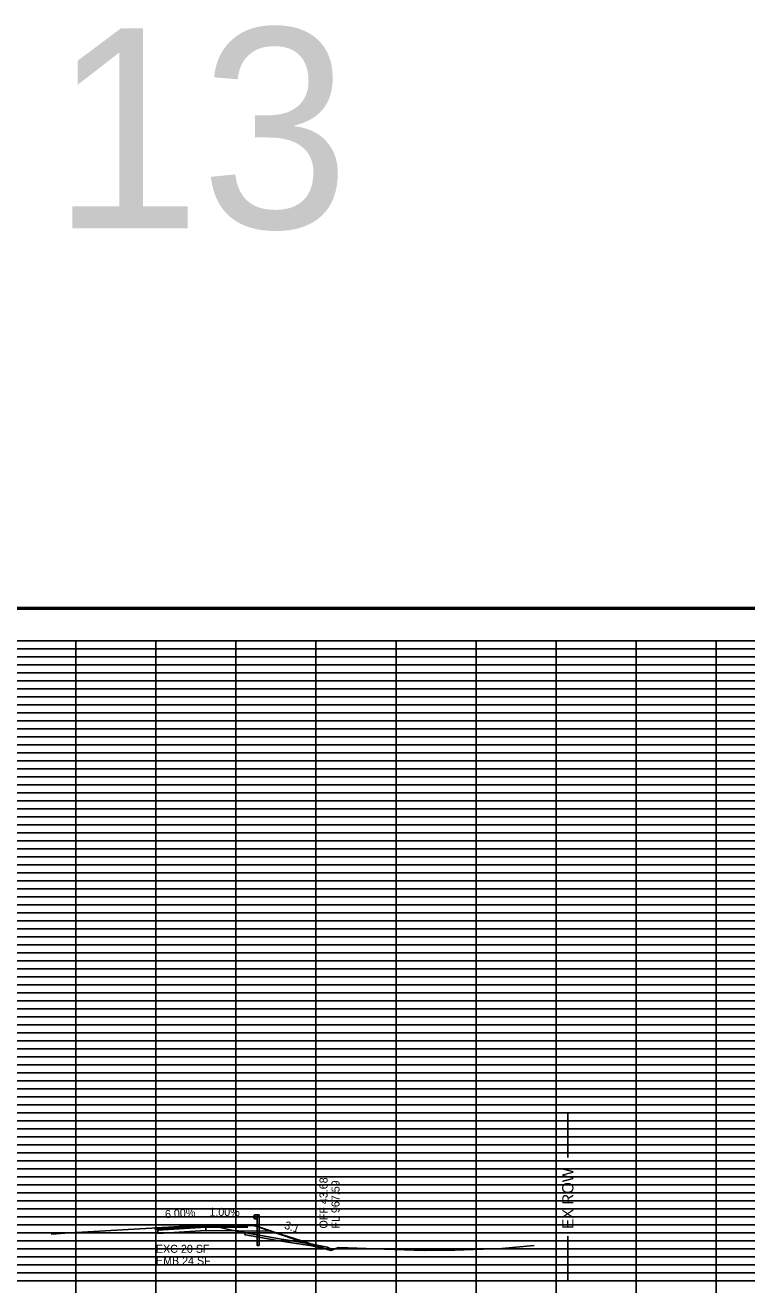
# Model space of a CAD drawing. Extents: x 2313580 to 2322968, y 282099 to 303247.
# Drawn here: x 2317959.8 to 2318140.1, y 287846.7 to 288161.5 of the extents above; entities that cross this region are included whole.
import ezdxf

# ---------------------------------------------------------------- set-up
doc = ezdxf.new("R2010")
doc.units = 0
for name, color, linetype in [('DESIGN - CENTERLINE - Proposed', 7, 'Continuous'), ('DESIGN - DRAINAGE - Text', 7, 'Continuous'), ('DESIGN - EARTHWORK - Excavation Limit Lines', 7, 'Continuous'), ('DESIGN - EARTHWORK - Shapes', 7, 'Continuous'), ('DESIGN - SCRATCH - User 1', 7, 'Continuous'), ('DESIGN - SCRATCH - User 5', 7, 'Continuous'), ('DESIGN - SHEET - Light Grid', 7, 'Continuous'), ('DESIGN - SHEET - Linework', 7, 'Continuous'), ('DESIGN - SHEET - Plot Shape', 7, 'Continuous'), ('DESIGN - TYPICAL - Finished Grade and Subgrade', 7, 'Continuous'), ('DESIGN - TYPICAL - Finished Grade Slopes Text', 7, 'Continuous'), ('DESIGN - TYPICAL - Guardrail', 7, 'Continuous'), ('Scratch Level', 7, 'Continuous'), ('SURVEY - GROUND - Top of Ground', 7, 'Continuous'), ('SURVEY - PROPERTY - ROW Lines Text', 7, 'Continuous')]:
    doc.layers.add(name, color=color, linetype=linetype)

# ---------------------------------------------------------------- blocks, each defined once
blk = doc.blocks.new('GRTYP')
at = {"layer": 'DESIGN - CENTERLINE - Proposed'}
for p, q in [((0.162, 0.37), (0.162, 0.37)), ((0.162, 0.37), (0.162, 0.37)), ((0.264, 0.37), (0.264, 0.37)), ((0.264, 0.37), (0.264, 0.37))]:
    blk.add_line(p, q, dxfattribs=at)
for points in [[(0.059, 0.567), (0.04, 0.563), (0.004, 0.539), (0, 0.531), (0.004, 0.523), (0.055, 0.492), (0.059, 0.484), (0.059, 0.464), (0.055, 0.456), (0.004, 0.425), (0, 0.417), (0.004, 0.409), (0.04, 0.385), (0.059, 0.382)], [(0.162, 0.374), (0.059, 0.374), (0.059, 0.574), (0.162, 0.574)], [(0.264, -0.126), (0.264, 0.574), (0.162, 0.574), (0.162, -0.075)], [(0.162, -0.075), (0.162, -0.949), (0.264, -0.949), (0.264, -0.122)]]:
    blk.add_lwpolyline(points, dxfattribs=at)

msp = doc.modelspace()

# ---------------------------------------------------------------- linework, layer by layer
at = {"layer": 'DESIGN - EARTHWORK - Shapes'}
for points in [[(2317992.31, 287860.88), (2317992.31, 287860.88), (2317997.49, 287861.18), (2318006.42, 287861.16), (2318007.84, 287861.15), (2318009.62, 287860.72), (2318010.94, 287860.43), (2318012.34, 287860.17), (2318004.93, 287860.25), (2317992.93, 287859.52), (2317992.93, 287860.35), (2317992.93, 287860.6), (2317992.31, 287860.57), (2317992.31, 287860.78)], [(2318012.34, 287860.17), (2318014.93, 287859.69), (2318023.84, 287858.07), (2318030.91, 287856.97), (2318021.79, 287859.94), (2318021.34, 287860.08), (2318021.16, 287860.08)], [(2318035, 287855.64), (2318035.2, 287855.57), (2318035.13, 287855.61)], [(2318035.47, 287855.49), (2318036.16, 287855.26), (2318035.92, 287855.75), (2318035.47, 287856)]]:
    msp.add_lwpolyline(points, close=True, dxfattribs=at)
at = {"layer": 'DESIGN - SCRATCH - User 1'}
msp.add_lwpolyline([(2318014.93, 287861.54), (2318016.93, 287861.52), (2318033.95, 287855.74)], dxfattribs=at)
msp.add_lwpolyline([(2318014.93, 287861.54), (2318016.93, 287861.52), (2318033.95, 287855.74)], dxfattribs=at)
msp.add_lwpolyline([(2318014.93, 287861.54), (2318016.93, 287861.52), (2318033.95, 287855.74)], dxfattribs=at)
msp.add_lwpolyline([(2318014.93, 287861.54), (2318016.93, 287861.52), (2318033.95, 287855.74)], dxfattribs=at)
at = {"layer": 'DESIGN - SCRATCH - User 5'}
for points in [[(2318030.91, 287856.97), (2318023.84, 287858.07), (2318014.93, 287859.69), (2318014.71, 287859.73), (2318014.71, 287859.22), (2318014.84, 287859.19), (2318023.75, 287857.58), (2318030.91, 287856.46)], [(2318030.91, 287856.97), (2318023.84, 287858.07), (2318014.93, 287859.69), (2318014.71, 287859.73), (2318014.71, 287859.22), (2318014.84, 287859.19), (2318023.75, 287857.58), (2318030.91, 287856.46)], [(2318030.91, 287856.46), (2318031.46, 287856.38), (2318035.13, 287855.61), (2318035.47, 287855.43), (2318035.47, 287856), (2318035.3, 287856.09), (2318031.55, 287856.87), (2318030.91, 287856.97)], [(2318030.91, 287856.46), (2318031.46, 287856.38), (2318035.13, 287855.61), (2318035.47, 287855.43), (2318035.47, 287856), (2318035.3, 287856.09), (2318031.55, 287856.87), (2318030.91, 287856.97)]]:
    msp.add_lwpolyline(points, close=True, dxfattribs=at)
at = {"layer": 'DESIGN - SHEET - Light Grid'}
for p, q in [((2317832.48, 288005.67), (2317992.48, 288005.67)), ((2317992.48, 288005.67), (2318152.48, 288005.67)), ((2317832.48, 288003.67), (2317992.48, 288003.67)), ((2317832.48, 288001.67), (2317992.48, 288001.67)), ((2317992.48, 288003.67), (2318152.48, 288003.67)), ((2317992.48, 288001.67), (2318152.48, 288001.67)), ((2317832.48, 287999.67), (2317992.48, 287999.67)), ((2317992.48, 287999.67), (2318152.48, 287999.67)), ((2317832.48, 287997.67), (2317992.48, 287997.67)), ((2317832.48, 287995.67), (2317992.48, 287995.67)), ((2317992.48, 287997.67), (2318152.48, 287997.67)), ((2317992.48, 287995.67), (2318152.48, 287995.67)), ((2317832.48, 287993.67), (2317992.48, 287993.67)), ((2317832.48, 287991.67), (2317992.48, 287991.67)), ((2317992.48, 287993.67), (2318152.48, 287993.67)), ((2317992.48, 287991.67), (2318152.48, 287991.67)), ((2317832.48, 287989.67), (2317992.48, 287989.67)), ((2317992.48, 287989.67), (2318152.48, 287989.67)), ((2317832.48, 287985.67), (2317992.48, 287985.67)), ((2317992.48, 287985.67), (2318152.48, 287985.67)), ((2317832.48, 287983.67), (2317992.48, 287983.67)), ((2317992.48, 287983.67), (2318152.48, 287983.67)), ((2317832.48, 287981.67), (2317992.48, 287981.67)), ((2317832.48, 287979.67), (2317992.48, 287979.67)), ((2317992.48, 287981.67), (2318152.48, 287981.67)), ((2317992.48, 287979.67), (2318152.48, 287979.67)), ((2317832.48, 287977.67), (2317992.48, 287977.67)), ((2317992.48, 287977.67), (2318152.48, 287977.67)), ((2317832.48, 287975.67), (2317992.48, 287975.67)), ((2317832.48, 287973.67), (2317992.48, 287973.67)), ((2317992.48, 287975.67), (2318152.48, 287975.67)), ((2317992.48, 287973.67), (2318152.48, 287973.67)), ((2317832.48, 287971.67), (2317992.48, 287971.67)), ((2317832.48, 287969.67), (2317992.48, 287969.67)), ((2317992.48, 287971.67), (2318152.48, 287971.67)), ((2317992.48, 287969.67), (2318152.48, 287969.67)), ((2317832.48, 287965.67), (2317992.48, 287965.67)), ((2317832.48, 287963.67), (2317992.48, 287963.67)), ((2317992.48, 287965.67), (2318152.48, 287965.67)), ((2317992.48, 287963.67), (2318152.48, 287963.67)), ((2317832.48, 287961.67), (2317992.48, 287961.67)), ((2317992.48, 287961.67), (2318152.48, 287961.67)), ((2317832.48, 287959.67), (2317992.48, 287959.67)), ((2317832.48, 287957.67), (2317992.48, 287957.67)), ((2317992.48, 287959.67), (2318152.48, 287959.67)), ((2317992.48, 287957.67), (2318152.48, 287957.67)), ((2317832.48, 287955.67), (2317992.48, 287955.67)), ((2317992.48, 287955.67), (2318152.48, 287955.67)), ((2317832.48, 287953.67), (2317992.48, 287953.67)), ((2317832.48, 287951.67), (2317992.48, 287951.67)), ((2317992.48, 287953.67), (2318152.48, 287953.67)), ((2317992.48, 287951.67), (2318152.48, 287951.67)), ((2317832.48, 287949.67), (2317992.48, 287949.67)), ((2317992.48, 287949.67), (2318152.48, 287949.67)), ((2317832.48, 287945.67), (2317992.48, 287945.67)), ((2317992.48, 287945.67), (2318152.48, 287945.67)), ((2317832.48, 287943.67), (2317992.48, 287943.67)), ((2317832.48, 287941.67), (2317992.48, 287941.67)), ((2317992.48, 287943.67), (2318152.48, 287943.67)), ((2317992.48, 287941.67), (2318152.48, 287941.67)), ((2317832.48, 287939.67), (2317992.48, 287939.67)), ((2317992.48, 287939.67), (2318152.48, 287939.67)), ((2317832.48, 287937.67), (2317992.48, 287937.67)), ((2317832.48, 287935.67), (2317992.48, 287935.67)), ((2317992.48, 287937.67), (2318152.48, 287937.67)), ((2317992.48, 287935.67), (2318152.48, 287935.67)), ((2317832.48, 287933.67), (2317992.48, 287933.67)), ((2317992.48, 287933.67), (2318152.48, 287933.67)), ((2317832.48, 287931.67), (2317992.48, 287931.67)), ((2317832.48, 287929.67), (2317992.48, 287929.67)), ((2317992.48, 287931.67), (2318152.48, 287931.67)), ((2317992.48, 287929.67), (2318152.48, 287929.67)), ((2317832.48, 287925.67), (2317992.48, 287925.67)), ((2317992.48, 287925.67), (2318152.48, 287925.67)), ((2317832.48, 287923.67), (2317992.48, 287923.67)), ((2317992.48, 287923.67), (2318152.48, 287923.67)), ((2317832.48, 287921.67), (2317992.48, 287921.67)), ((2317832.48, 287919.67), (2317992.48, 287919.67)), ((2317992.48, 287921.67), (2318152.48, 287921.67)), ((2317992.48, 287919.67), (2318152.48, 287919.67)), ((2317832.48, 287917.67), (2317992.48, 287917.67)), ((2317992.48, 287917.67), (2318152.48, 287917.67)), ((2317832.48, 287915.67), (2317992.48, 287915.67)), ((2317832.48, 287913.67), (2317992.48, 287913.67)), ((2317992.48, 287915.67), (2318152.48, 287915.67)), ((2317992.48, 287913.67), (2318152.48, 287913.67)), ((2317832.48, 287911.67), (2317992.48, 287911.67)), ((2317992.48, 287911.67), (2318152.48, 287911.67)), ((2317832.48, 287909.67), (2317992.48, 287909.67)), ((2317992.48, 287909.67), (2318152.48, 287909.67)), ((2317832.48, 287905.67), (2317992.48, 287905.67)), ((2317832.48, 287903.67), (2317992.48, 287903.67)), ((2317992.48, 287905.67), (2318152.48, 287905.67)), ((2317992.48, 287903.67), (2318152.48, 287903.67)), ((2317832.48, 287901.67), (2317992.48, 287901.67)), ((2317992.48, 287901.67), (2318152.48, 287901.67)), ((2317832.48, 287899.67), (2317992.48, 287899.67)), ((2317832.48, 287897.67), (2317992.48, 287897.67)), ((2317992.48, 287899.67), (2318152.48, 287899.67)), ((2317992.48, 287897.67), (2318152.48, 287897.67)), ((2317832.48, 287895.67), (2317992.48, 287895.67)), ((2317992.48, 287895.67), (2318152.48, 287895.67)), ((2317832.48, 287893.67), (2317992.48, 287893.67)), ((2317832.48, 287891.67), (2317992.48, 287891.67)), ((2317992.48, 287893.67), (2318152.48, 287893.67)), ((2317992.48, 287891.67), (2318152.48, 287891.67)), ((2317832.48, 287889.67), (2317992.48, 287889.67)), ((2317992.48, 287889.67), (2318152.48, 287889.67)), ((2317832.48, 287885.67), (2317992.48, 287885.67)), ((2317992.48, 287885.67), (2318152.48, 287885.67)), ((2317832.48, 287883.67), (2317992.48, 287883.67)), ((2317832.48, 287881.67), (2317992.48, 287881.67)), ((2317992.48, 287883.67), (2318152.48, 287883.67)), ((2317992.48, 287881.67), (2318152.48, 287881.67)), ((2317832.48, 287879.67), (2317992.48, 287879.67)), ((2317992.48, 287879.67), (2318152.48, 287879.67)), ((2317832.48, 287877.67), (2317992.48, 287877.67)), ((2317832.48, 287875.67), (2317992.48, 287875.67)), ((2317992.48, 287877.67), (2318152.48, 287877.67)), ((2317992.48, 287875.67), (2318152.48, 287875.67)), ((2317832.48, 287873.67), (2317992.48, 287873.67)), ((2317992.48, 287873.67), (2318152.48, 287873.67)), ((2317832.48, 287871.67), (2317992.48, 287871.67)), ((2317832.48, 287869.67), (2317992.48, 287869.67)), ((2317992.48, 287871.67), (2318152.48, 287871.67)), ((2317992.48, 287869.67), (2318152.48, 287869.67)), ((2317832.48, 287865.67), (2317992.48, 287865.67)), ((2317992.48, 287865.67), (2318152.48, 287865.67)), ((2317832.48, 287863.67), (2317992.48, 287863.67)), ((2317992.48, 287863.67), (2318152.48, 287863.67)), ((2317832.48, 287861.67), (2317992.48, 287861.67)), ((2317832.48, 287859.67), (2317992.48, 287859.67)), ((2317992.48, 287861.67), (2318152.48, 287861.67)), ((2317992.48, 287859.67), (2318152.48, 287859.67)), ((2317832.48, 287857.67), (2317992.48, 287857.67)), ((2317992.48, 287857.67), (2318152.48, 287857.67)), ((2317832.48, 287855.67), (2317992.48, 287855.67)), ((2317832.48, 287853.67), (2317992.48, 287853.67)), ((2317992.48, 287855.67), (2318152.48, 287855.67)), ((2317992.48, 287853.67), (2318152.48, 287853.67)), ((2317832.48, 287851.67), (2317992.48, 287851.67)), ((2317992.48, 287851.67), (2318152.48, 287851.67)), ((2317832.48, 287849.67), (2317992.48, 287849.67)), ((2317992.48, 287849.67), (2318152.48, 287849.67))]:
    msp.add_line(p, q, dxfattribs=at)
at = {"layer": 'DESIGN - SHEET - Linework'}
for p, q in [((2317636.02, 288015.95), (2318316.82, 288015.95)), ((2317972.48, 287587.67), (2317972.48, 288007.67)), ((2317992.48, 287587.67), (2317992.48, 288007.67)), ((2318012.48, 287587.67), (2318012.48, 288007.67)), ((2318032.48, 287587.67), (2318032.48, 288007.67)), ((2318052.48, 287587.67), (2318052.48, 288007.67)), ((2318072.48, 287587.67), (2318072.48, 288007.67)), ((2318092.48, 287587.67), (2318092.48, 288007.67)), ((2318112.48, 287587.67), (2318112.48, 288007.67)), ((2318132.48, 287587.67), (2318132.48, 288007.67)), ((2317672.48, 287987.67), (2318232.48, 287987.67)), ((2317672.48, 287967.67), (2318312.48, 287967.67)), ((2317672.48, 287947.67), (2318312.48, 287947.67)), ((2317672.48, 287927.67), (2318312.48, 287927.67)), ((2317672.48, 287907.67), (2318312.48, 287907.67)), ((2317672.48, 287887.67), (2318312.48, 287887.67)), ((2317672.48, 287867.67), (2318312.48, 287867.67)), ((2317672.48, 287847.67), (2318312.48, 287847.67))]:
    msp.add_line(p, q, dxfattribs=at)
msp.add_lwpolyline([(2317672.48, 288007.67), (2317672.48, 287587.67), (2318312.48, 287587.67), (2318312.48, 288007.67), (2317672.48, 288007.67)], dxfattribs=at)
at = {"layer": 'DESIGN - SHEET - Plot Shape'}
for points in [[(2317636.42, 288015.55), (2318316.42, 288015.55), (2318316.42, 287579.79), (2317636.42, 287579.79)], [(2317655.48, 288007.67), (2318312.48, 288007.67), (2318312.48, 287582.67), (2317655.48, 287582.67)]]:
    msp.add_lwpolyline(points, close=True, dxfattribs=at)
at = {"layer": 'DESIGN - TYPICAL - Finished Grade and Subgrade'}
msp.add_lwpolyline([(2317992.31, 287860.88), (2317992.39, 287860.89), (2317992.93, 287860.92), (2317994.38, 287861), (2318004.93, 287861.64), (2318006.15, 287861.62), (2318014.93, 287861.54), (2318015.18, 287861.53), (2318016.93, 287861.52), (2318017.37, 287861.38), (2318021.34, 287860.08), (2318021.79, 287859.94), (2318036.16, 287855.26)], dxfattribs=at)
for points in [[(2317992.93, 287860.92), (2317992.31, 287860.88), (2317992.31, 287860.78), (2317992.93, 287860.81)], [(2317992.93, 287860.81), (2317992.93, 287860.6), (2317992.31, 287860.57), (2317992.31, 287860.78)], [(2317992.93, 287860.92), (2318004.93, 287861.64), (2318004.93, 287861.54), (2317992.93, 287860.81)], [(2317992.93, 287860.81), (2318004.93, 287861.54), (2318004.93, 287861.33), (2317992.93, 287860.6)], [(2317992.93, 287860.6), (2318004.93, 287861.33), (2318004.93, 287861.08), (2317992.93, 287860.35)], [(2317992.93, 287860.35), (2318004.93, 287861.08), (2318004.93, 287860.25), (2317992.93, 287859.52)], [(2318004.93, 287861.64), (2318014.93, 287861.54), (2318014.93, 287861.44), (2318004.93, 287861.54)], [(2318004.93, 287861.08), (2318015.24, 287860.98), (2318015.24, 287861.23), (2318015.04, 287861.23), (2318015.04, 287861.44), (2318014.93, 287861.44), (2318014.93, 287861.54), (2318016.93, 287861.52), (2318021.34, 287860.08), (2318004.93, 287860.25)], [(2318004.93, 287861.54), (2318015.04, 287861.44), (2318015.04, 287861.23), (2318004.93, 287861.33)], [(2318004.93, 287861.33), (2318015.24, 287861.23), (2318015.24, 287860.98), (2318004.93, 287861.08)]]:
    msp.add_lwpolyline(points, close=True, dxfattribs=at)
at = {"layer": 'Scratch Level'}
for points in [[(2317992.31, 287860.88), (2317992.31, 287860.88), (2317997.49, 287861.18), (2318006.42, 287861.16), (2318007.84, 287861.15), (2318009.62, 287860.72), (2318010.94, 287860.43), (2318012.34, 287860.17), (2318004.93, 287860.25), (2317992.93, 287859.52), (2317992.93, 287860.35), (2317992.93, 287860.6), (2317992.31, 287860.57), (2317992.31, 287860.78)], [(2318012.34, 287860.17), (2318014.93, 287859.69), (2318023.84, 287858.07), (2318030.91, 287856.97), (2318021.79, 287859.94), (2318021.34, 287860.08), (2318021.16, 287860.08)], [(2318035, 287855.64), (2318035.2, 287855.57), (2318035.13, 287855.61)], [(2318035.47, 287855.49), (2318036.16, 287855.26), (2318035.92, 287855.75), (2318035.47, 287856)]]:
    msp.add_lwpolyline(points, close=True, dxfattribs=at)
at = {"layer": 'SURVEY - GROUND - Top of Ground'}
msp.add_lwpolyline([(2317966.27, 287859.3), (2317967.53, 287859.41), (2317969.72, 287859.6), (2317988.45, 287860.67), (2317997.49, 287861.18), (2318006.42, 287861.16), (2318007.84, 287861.15), (2318009.62, 287860.72), (2318010.94, 287860.43), (2318014.93, 287859.69), (2318023.84, 287858.07), (2318031.55, 287856.87), (2318035.3, 287856.09), (2318035.92, 287855.75), (2318036.16, 287855.26), (2318038.14, 287855.96), (2318049.58, 287855.54), (2318059.49, 287855.24), (2318067.21, 287855.32), (2318078.89, 287855.73), (2318087.04, 287856.5)], dxfattribs=at)
at = {"layer": 'SURVEY - PROPERTY - ROW Lines Text'}
for p, q in [((2318095.41, 287889.67), (2318095.41, 287878.47)), ((2318095.41, 287847.67), (2318095.41, 287858.87))]:
    msp.add_line(p, q, dxfattribs=at)

# ---------------------------------------------------------------- block references
at = {"layer": 'DESIGN - TYPICAL - Guardrail', "xscale": 5, "yscale": 5}
msp.add_blockref('GRTYP', (2318016.93, 287861.26), dxfattribs=at)

# ---------------------------------------------------------------- texts
at = {"layer": 'DESIGN - DRAINAGE - Text'}
for s, p in [("OFF 43.68'", (2318035.36, 287860.74)), ('FL 967.59', (2318038.36, 287860.74))]:
    msp.add_text(s, height=2, rotation=90, dxfattribs=at).set_placement(p)
at = {"layer": 'DESIGN - EARTHWORK - Excavation Limit Lines'}
for s, p in [('EXC 20 SF', (2317992.48, 287854.67)), ('EMB 24 SF', (2317992.48, 287851.67))]:
    msp.add_text(s, height=2, dxfattribs=at).set_placement(p)
at = {"layer": 'DESIGN - SCRATCH - User 1'}
msp.add_text('13', height=50, dxfattribs=at).set_placement((2317966.49, 288110.78))
at = {"layer": 'DESIGN - TYPICAL - Finished Grade Slopes Text'}
for s, rotation, p in [('6.00%', 3.4342, (2317994.8, 287863.33)), ('1.00%', 359.4276, (2318005.83, 287863.93)), ('3:1', 341.849, (2318024.42, 287860.77))]:
    msp.add_text(s, height=2, rotation=rotation, dxfattribs=at).set_placement(p)
at = {"layer": 'SURVEY - PROPERTY - ROW Lines Text'}
msp.add_text('EX ROW', height=2.8, rotation=90, dxfattribs=at).set_placement((2318096.81, 287860.67))

doc.saveas('drawing.dxf')
